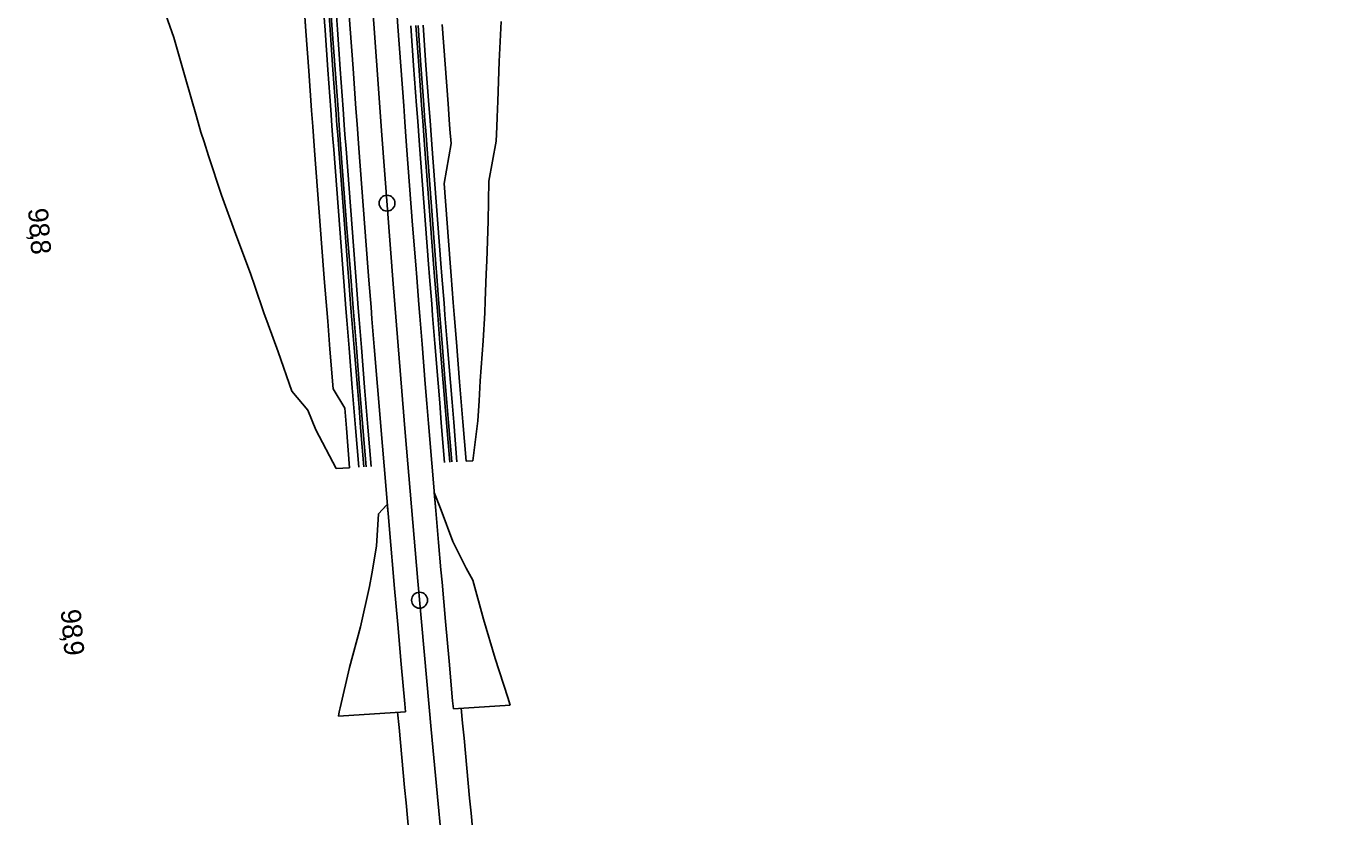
# Model space of a CAD drawing. Extents: x -678487 to -674601, y -1104811 to -1093295.
# Drawn here: x -677536.8 to -677205.5, y -1095748.7 to -1095550.4 of the extents above; entities that cross this region are included whole.
import ezdxf

# ---------------------------------------------------------------- set-up
doc = ezdxf.new("R2010")
doc.units = 0
for name, color, linetype in [('00_MiNGO', 7, 'Continuous'), ('SOxxxxxx_Osa_bod_P', 7, 'Continuous'), ('SOxxxxxx_Staničení_Popis', 7, 'Continuous'), ('SOxxxxxx_ŽSp_hrana', 7, 'Continuous'), ('SOxxxxxx_ŽSp_násyp_hrana', 7, 'Continuous'), ('SOxxxxxx_ŽSp_násyp_plocha', 7, 'Continuous'), ('SOxxxxxx_ŽSp_odvodnění', 7, 'Continuous'), ('SOxxxxxx_ŽSp_zářez_hrana', 7, 'Continuous'), ('SOxxxxxx_ŽSp_zářez_plocha', 7, 'Continuous')]:
    doc.layers.add(name, color=color, linetype=linetype)

msp = doc.modelspace()

# ---------------------------------------------------------------- linework, layer by layer
at = {"layer": '00_MiNGO'}
for radius, start in [(8510.25, 185.218154), (8494.25, 185.221143)]:
    msp.add_arc((-668968.6, -1094948.57), radius, start, 186.854762, dxfattribs=at)
at = {"layer": 'SOxxxxxx_Osa_bod_P'}
msp.add_arc((-668968.6, -1094948.57), 8502.25, 183.991255, 200.113006, dxfattribs=at)
at = {"layer": 'SOxxxxxx_Staničení_Popis'}
for p, q in [((-677446.25, -1095594.77), (-677446.25, -1095594.77)), ((-677438.07, -1095694.43), (-677438.07, -1095694.43))]:
    msp.add_line(p, q, dxfattribs=at)
for centre in [(-677446.25, -1095594.77), (-677438.07, -1095694.43)]:
    msp.add_circle(centre, 2, dxfattribs=at)
at = {"layer": 'SOxxxxxx_ŽSp_hrana'}
for p, q in [((-677456.2, -1095541.06), (-677455.5, -1095551.04)), ((-677444.19, -1095540.47), (-677443.49, -1095550.44)), ((-677455.5, -1095551.04), (-677454.78, -1095561.01)), ((-677443.49, -1095550.44), (-677442.78, -1095560.41)), ((-677454.78, -1095561.01), (-677454.06, -1095570.99)), ((-677442.78, -1095560.41), (-677442.05, -1095570.38)), ((-677454.06, -1095570.99), (-677453.77, -1095574.94)), ((-677442.05, -1095570.38), (-677441.76, -1095574.33)), ((-677441.76, -1095574.33), (-677441.58, -1095576.77)), ((-677453.77, -1095574.94), (-677453.59, -1095577.38)), ((-677453.59, -1095577.38), (-677453.32, -1095580.96)), ((-677441.58, -1095576.77), (-677441.32, -1095580.35)), ((-677453.32, -1095580.96), (-677452.57, -1095590.93)), ((-677441.32, -1095580.35), (-677440.57, -1095590.31)), ((-677452.57, -1095590.93), (-677451.81, -1095600.9)), ((-677440.57, -1095590.31), (-677439.81, -1095600.27)), ((-677439.81, -1095600.27), (-677439.03, -1095610.24)), ((-677451.81, -1095600.9), (-677451.04, -1095610.87)), ((-677439.03, -1095610.24), (-677438.78, -1095613.45)), ((-677451.04, -1095610.87), (-677450.79, -1095614.09)), ((-677450.79, -1095614.09), (-677450.25, -1095620.84)), ((-677438.78, -1095613.45), (-677438.25, -1095620.2)), ((-677438.25, -1095620.2), (-677438.01, -1095623.16)), ((-677450.25, -1095620.84), (-677450.02, -1095623.81)), ((-677450.02, -1095623.81), (-677449.46, -1095630.81)), ((-677438.01, -1095623.16), (-677437.45, -1095630.15)), ((-677437.45, -1095630.15), (-677436.65, -1095640.11)), ((-677449.46, -1095630.81), (-677448.65, -1095640.78)), ((-677436.65, -1095640.11), (-677436.24, -1095645.09)), ((-677448.65, -1095640.78), (-677448.24, -1095645.76)), ((-677448.24, -1095645.76), (-677447.83, -1095650.8)), ((-677436.24, -1095645.09), (-677435.82, -1095650.12)), ((-677435.82, -1095650.12), (-677435, -1095660.02)), ((-677447.83, -1095650.8), (-677447, -1095660.7)), ((-677435, -1095660.02), (-677434.16, -1095669.97)), ((-677447, -1095660.7), (-677446.16, -1095670.67)), ((-677434.16, -1095669.97), (-677433.99, -1095671.94)), ((-677446.16, -1095670.67), (-677445.99, -1095672.64)), ((-677445.99, -1095672.64), (-677445.3, -1095680.63)), ((-677433.99, -1095671.94), (-677433.3, -1095679.92)), ((-677433.3, -1095679.92), (-677432.71, -1095686.77)), ((-677445.3, -1095680.63), (-677444.71, -1095687.49)), ((-677432.71, -1095686.77), (-677432.44, -1095689.87)), ((-677444.71, -1095687.49), (-677444.44, -1095690.59)), ((-677432.44, -1095689.87), (-677431.56, -1095699.81)), ((-677444.44, -1095690.59), (-677443.56, -1095700.54)), ((-677431.56, -1095699.81), (-677430.67, -1095709.75)), ((-677443.56, -1095700.54), (-677442.67, -1095710.5)), ((-677430.67, -1095709.75), (-677429.77, -1095719.7)), ((-677442.67, -1095710.5), (-677441.77, -1095720.45)), ((-677429.77, -1095719.7), (-677429.59, -1095721.67)), ((-677441.77, -1095720.45), (-677441.59, -1095722.44))]:
    msp.add_line(p, q, dxfattribs=at)
at = {"layer": 'SOxxxxxx_ŽSp_násyp_hrana'}
for p, q in [((-677433.41, -1095669.93), (-677432.67, -1095671.87)), ((-677448.35, -1095672.78), (-677448.88, -1095680.84)), ((-677446.45, -1095670.68), (-677448.35, -1095672.78)), ((-677432.67, -1095671.87), (-677429.73, -1095679.71)), ((-677429.73, -1095679.71), (-677426.4, -1095686.4)), ((-677448.88, -1095680.84), (-677450.09, -1095687.81)), ((-677426.4, -1095686.4), (-677424.73, -1095689.4)), ((-677450.09, -1095687.81), (-677450.63, -1095690.96)), ((-677424.73, -1095689.4), (-677422.04, -1095699.23)), ((-677450.63, -1095690.96), (-677452.93, -1095701.12)), ((-677422.04, -1095699.23), (-677419.11, -1095709.04)), ((-677452.93, -1095701.12), (-677455.68, -1095711.31)), ((-677419.11, -1095709.04), (-677415.95, -1095718.82)), ((-677455.68, -1095711.31), (-677458, -1095721.48)), ((-677415.95, -1095718.82), (-677415.32, -1095720.77)), ((-677458.24, -1095722.49), (-677458.47, -1095723.51)), ((-677458, -1095721.48), (-677458.24, -1095722.49))]:
    msp.add_line(p, q, dxfattribs=at)
at = {"layer": 'SOxxxxxx_ŽSp_násyp_plocha'}
for p, q in [((-677458.47, -1095723.51), (-677441.59, -1095722.44)), ((-677415.32, -1095720.77), (-677429.59, -1095721.67))]:
    msp.add_line(p, q, dxfattribs=at)
for points in [[(-677446.18, -1095670.38), (-677448.35, -1095672.78), (-677448.88, -1095680.84), (-677450.09, -1095687.81), (-677450.63, -1095690.96), (-677452.93, -1095701.12), (-677455.68, -1095711.31), (-677458, -1095721.48), (-677458.24, -1095722.49), (-677458.47, -1095723.51)], [(-677441.59, -1095722.44), (-677441.77, -1095720.45), (-677442.67, -1095710.5), (-677443.56, -1095700.54), (-677444.44, -1095690.59), (-677444.71, -1095687.49), (-677445.3, -1095680.63), (-677445.99, -1095672.64), (-677446.18, -1095670.38)], [(-677429.59, -1095721.67), (-677429.77, -1095719.7), (-677430.67, -1095709.75), (-677431.56, -1095699.81), (-677432.44, -1095689.87), (-677432.71, -1095686.77), (-677433.3, -1095679.92), (-677433.99, -1095671.94), (-677434.38, -1095667.37)], [(-677434.38, -1095667.37), (-677432.67, -1095671.87), (-677429.73, -1095679.71), (-677426.4, -1095686.4), (-677424.73, -1095689.4), (-677422.04, -1095699.23), (-677419.11, -1095709.04), (-677415.95, -1095718.82), (-677415.32, -1095720.77)]]:
    msp.add_lwpolyline(points, dxfattribs=at)
at = {"layer": 'SOxxxxxx_ŽSp_odvodnění'}
for p, q in [((-677461.24, -1095541.31), (-677460.54, -1095551.29)), ((-677460.69, -1095541.28), (-677459.99, -1095551.26)), ((-677439, -1095550.22), (-677438.28, -1095560.19)), ((-677438.45, -1095550.19), (-677437.73, -1095560.16)), ((-677460.54, -1095551.29), (-677459.83, -1095561.27)), ((-677459.99, -1095551.26), (-677459.28, -1095561.24)), ((-677438.28, -1095560.19), (-677437.56, -1095570.15)), ((-677437.73, -1095560.16), (-677437.01, -1095570.13)), ((-677459.83, -1095561.27), (-677459.1, -1095571.24)), ((-677459.28, -1095561.24), (-677458.55, -1095571.21)), ((-677437.56, -1095570.15), (-677437.27, -1095574.11)), ((-677437.01, -1095570.13), (-677436.72, -1095574.08)), ((-677459.1, -1095571.24), (-677458.81, -1095575.2)), ((-677458.55, -1095571.21), (-677458.26, -1095575.17)), ((-677437.27, -1095574.11), (-677437.09, -1095576.54)), ((-677436.72, -1095574.08), (-677436.54, -1095576.51)), ((-677458.81, -1095575.2), (-677458.63, -1095577.64)), ((-677458.63, -1095577.64), (-677458.36, -1095581.22)), ((-677458.26, -1095575.17), (-677458.08, -1095577.61)), ((-677458.08, -1095577.61), (-677457.81, -1095581.19)), ((-677437.09, -1095576.54), (-677436.82, -1095580.12)), ((-677436.54, -1095576.51), (-677436.27, -1095580.09)), ((-677436.82, -1095580.12), (-677436.07, -1095590.08)), ((-677436.27, -1095580.09), (-677435.52, -1095590.05)), ((-677458.36, -1095581.22), (-677457.61, -1095591.19)), ((-677457.81, -1095581.19), (-677457.06, -1095591.17)), ((-677436.07, -1095590.08), (-677435.31, -1095600.04)), ((-677435.52, -1095590.05), (-677434.76, -1095600.01)), ((-677457.61, -1095591.19), (-677456.85, -1095601.17)), ((-677457.06, -1095591.17), (-677456.3, -1095601.14)), ((-677435.31, -1095600.04), (-677434.54, -1095610)), ((-677434.76, -1095600.01), (-677433.99, -1095609.97)), ((-677456.85, -1095601.17), (-677456.08, -1095611.14)), ((-677456.3, -1095601.14), (-677455.53, -1095611.11)), ((-677434.54, -1095610), (-677434.29, -1095613.21)), ((-677433.99, -1095609.97), (-677433.74, -1095613.18)), ((-677456.08, -1095611.14), (-677455.83, -1095614.36)), ((-677455.53, -1095611.11), (-677455.28, -1095614.33)), ((-677434.29, -1095613.21), (-677433.76, -1095619.95)), ((-677433.74, -1095613.18), (-677433.21, -1095619.92)), ((-677455.83, -1095614.36), (-677455.3, -1095621.11)), ((-677455.28, -1095614.33), (-677454.75, -1095621.08)), ((-677433.76, -1095619.95), (-677433.52, -1095622.92)), ((-677433.21, -1095619.92), (-677432.97, -1095622.89)), ((-677455.3, -1095621.11), (-677455.06, -1095624.08)), ((-677454.75, -1095621.08), (-677454.51, -1095624.05)), ((-677454.51, -1095624.05), (-677453.95, -1095631.05)), ((-677433.52, -1095622.92), (-677432.96, -1095629.91)), ((-677432.97, -1095622.89), (-677432.41, -1095629.88)), ((-677455.06, -1095624.08), (-677454.5, -1095631.08)), ((-677432.96, -1095629.91), (-677432.15, -1095639.86)), ((-677432.41, -1095629.88), (-677431.61, -1095639.83)), ((-677454.5, -1095631.08), (-677453.69, -1095641.05)), ((-677453.95, -1095631.05), (-677453.14, -1095641.02)), ((-677432.15, -1095639.86), (-677431.75, -1095644.84)), ((-677431.61, -1095639.83), (-677431.2, -1095644.81)), ((-677453.69, -1095641.05), (-677453.28, -1095646.04)), ((-677453.14, -1095641.02), (-677452.73, -1095646.01)), ((-677453.28, -1095646.04), (-677452.87, -1095651.08)), ((-677452.73, -1095646.01), (-677452.32, -1095651.05)), ((-677431.75, -1095644.84), (-677431.33, -1095649.87)), ((-677431.2, -1095644.81), (-677430.78, -1095649.84)), ((-677431.33, -1095649.87), (-677430.51, -1095659.76)), ((-677430.78, -1095649.84), (-677429.96, -1095659.73)), ((-677452.87, -1095651.08), (-677452.04, -1095660.99)), ((-677452.32, -1095651.05), (-677451.49, -1095660.96))]:
    msp.add_line(p, q, dxfattribs=at)
at = {"layer": 'SOxxxxxx_ŽSp_zářez_hrana'}
for p, q in [((-677459.42, -1095541.22), (-677458.71, -1095551.2)), ((-677503.18, -1095543.37), (-677499.75, -1095553.23)), ((-677467.34, -1095541.61), (-677466.63, -1095551.59)), ((-677462.52, -1095541.37), (-677461.82, -1095551.35)), ((-677440.28, -1095550.28), (-677439.56, -1095560.25)), ((-677437.17, -1095550.13), (-677436.46, -1095560.1)), ((-677432.36, -1095549.89), (-677431.64, -1095559.86)), ((-677417.59, -1095549.16), (-677418.11, -1095559.18)), ((-677499.75, -1095553.23), (-677496.97, -1095563.12)), ((-677466.63, -1095551.59), (-677465.92, -1095561.57)), ((-677461.82, -1095551.35), (-677461.11, -1095561.33)), ((-677458.71, -1095551.2), (-677458, -1095561.17)), ((-677439.56, -1095560.25), (-677438.84, -1095570.22)), ((-677436.46, -1095560.1), (-677435.73, -1095570.06)), ((-677431.64, -1095559.86), (-677430.92, -1095569.82)), ((-677418.11, -1095559.18), (-677418.44, -1095569.19)), ((-677496.97, -1095563.12), (-677494.12, -1095573.01)), ((-677465.92, -1095561.57), (-677465.19, -1095571.55)), ((-677461.11, -1095561.33), (-677460.38, -1095571.31)), ((-677458, -1095561.17), (-677457.27, -1095571.15)), ((-677438.84, -1095570.22), (-677438.55, -1095574.17)), ((-677435.73, -1095570.06), (-677435.44, -1095574.01)), ((-677430.92, -1095569.82), (-677430.63, -1095573.77)), ((-677418.44, -1095569.19), (-677418.57, -1095573.16)), ((-677494.12, -1095573.01), (-677492.96, -1095576.93)), ((-677465.19, -1095571.55), (-677464.9, -1095575.51)), ((-677460.38, -1095571.31), (-677460.09, -1095575.26)), ((-677457.27, -1095571.15), (-677456.98, -1095575.11)), ((-677438.55, -1095574.17), (-677438.37, -1095576.6)), ((-677435.44, -1095574.01), (-677435.26, -1095576.45)), ((-677430.63, -1095573.77), (-677430.45, -1095576.2)), ((-677418.57, -1095573.16), (-677418.69, -1095575.6)), ((-677492.96, -1095576.93), (-677492.2, -1095579.35)), ((-677464.9, -1095575.51), (-677464.72, -1095577.95)), ((-677460.09, -1095575.26), (-677459.91, -1095577.7)), ((-677456.98, -1095575.11), (-677456.8, -1095577.54)), ((-677456.8, -1095577.54), (-677456.54, -1095581.13)), ((-677438.37, -1095576.6), (-677438.1, -1095580.18)), ((-677435.26, -1095576.45), (-677434.99, -1095580.02)), ((-677430.45, -1095576.2), (-677430.18, -1095579.78)), ((-677418.69, -1095575.6), (-677418.8, -1095579.2)), ((-677492.2, -1095579.35), (-677491.09, -1095582.89)), ((-677464.72, -1095577.95), (-677464.46, -1095581.53)), ((-677459.91, -1095577.7), (-677459.64, -1095581.28)), ((-677438.1, -1095580.18), (-677437.35, -1095590.14)), ((-677434.99, -1095580.02), (-677434.24, -1095589.98)), ((-677430.18, -1095579.78), (-677431.93, -1095589.86)), ((-677418.8, -1095579.2), (-677420.72, -1095589.28)), ((-677491.09, -1095582.89), (-677487.82, -1095592.76)), ((-677464.46, -1095581.53), (-677463.71, -1095591.51)), ((-677459.64, -1095581.28), (-677458.89, -1095591.26)), ((-677456.54, -1095581.13), (-677455.79, -1095591.1)), ((-677437.35, -1095590.14), (-677436.59, -1095600.11)), ((-677434.24, -1095589.98), (-677433.48, -1095599.94)), ((-677431.93, -1095589.86), (-677431.17, -1095599.82)), ((-677420.72, -1095589.28), (-677420.88, -1095599.28)), ((-677487.82, -1095592.76), (-677484.17, -1095602.6)), ((-677463.71, -1095591.51), (-677462.94, -1095601.49)), ((-677458.89, -1095591.26), (-677458.13, -1095601.23)), ((-677455.79, -1095591.1), (-677455.03, -1095601.07)), ((-677436.59, -1095600.11), (-677435.82, -1095610.07)), ((-677433.48, -1095599.94), (-677432.71, -1095609.9)), ((-677431.17, -1095599.82), (-677430.4, -1095609.78)), ((-677420.88, -1095599.28), (-677421.2, -1095609.29)), ((-677484.17, -1095602.6), (-677480.54, -1095612.44)), ((-677462.94, -1095601.49), (-677462.17, -1095611.46)), ((-677458.13, -1095601.23), (-677457.36, -1095611.21)), ((-677455.03, -1095601.07), (-677454.25, -1095611.04)), ((-677435.82, -1095610.07), (-677435.57, -1095613.28)), ((-677432.71, -1095609.9), (-677432.46, -1095613.11)), ((-677430.4, -1095609.78), (-677430.14, -1095612.99)), ((-677421.2, -1095609.29), (-677421.32, -1095612.52)), ((-677480.54, -1095612.44), (-677479.48, -1095615.62)), ((-677462.17, -1095611.46), (-677461.92, -1095614.69)), ((-677457.36, -1095611.21), (-677457.11, -1095614.43)), ((-677454.25, -1095611.04), (-677454, -1095614.26)), ((-677435.57, -1095613.28), (-677435.03, -1095620.02)), ((-677432.46, -1095613.11), (-677431.93, -1095619.86)), ((-677430.14, -1095612.99), (-677429.61, -1095619.73)), ((-677421.32, -1095612.52), (-677421.58, -1095619.3)), ((-677479.48, -1095615.62), (-677477.15, -1095622.29)), ((-677461.92, -1095614.69), (-677461.39, -1095621.44)), ((-677457.11, -1095614.43), (-677456.57, -1095621.18)), ((-677454, -1095614.26), (-677453.47, -1095621.01)), ((-677435.03, -1095620.02), (-677434.8, -1095622.98)), ((-677431.93, -1095619.86), (-677431.69, -1095622.82)), ((-677429.61, -1095619.73), (-677429.38, -1095622.69)), ((-677421.58, -1095619.3), (-677421.69, -1095622.28)), ((-677477.15, -1095622.29), (-677476.07, -1095625.21)), ((-677461.39, -1095621.44), (-677461.15, -1095624.41)), ((-677456.57, -1095621.18), (-677456.34, -1095624.15)), ((-677453.47, -1095621.01), (-677453.23, -1095623.98)), ((-677453.23, -1095623.98), (-677452.67, -1095630.98)), ((-677434.8, -1095622.98), (-677434.24, -1095629.98)), ((-677431.69, -1095622.82), (-677431.13, -1095629.81)), ((-677429.38, -1095622.69), (-677428.82, -1095629.68)), ((-677421.69, -1095622.28), (-677422.08, -1095629.32)), ((-677476.07, -1095625.21), (-677473.54, -1095632.12)), ((-677461.15, -1095624.41), (-677460.59, -1095631.42)), ((-677456.34, -1095624.15), (-677455.78, -1095631.15)), ((-677434.24, -1095629.98), (-677433.43, -1095639.93)), ((-677431.13, -1095629.81), (-677430.33, -1095639.76)), ((-677428.82, -1095629.68), (-677428.01, -1095639.63)), ((-677422.08, -1095629.32), (-677422.86, -1095639.35)), ((-677473.54, -1095632.12), (-677470.19, -1095641.97)), ((-677460.59, -1095631.42), (-677459.78, -1095641.39)), ((-677455.78, -1095631.15), (-677454.97, -1095641.13)), ((-677452.67, -1095630.98), (-677451.86, -1095640.95)), ((-677433.43, -1095639.93), (-677433.02, -1095644.91)), ((-677430.33, -1095639.76), (-677429.92, -1095644.74)), ((-677428.01, -1095639.63), (-677427.6, -1095644.61)), ((-677422.86, -1095639.35), (-677423.08, -1095644.35)), ((-677470.19, -1095641.97), (-677466.09, -1095646.75)), ((-677459.78, -1095641.39), (-677456.88, -1095646.24)), ((-677454.97, -1095641.13), (-677454.56, -1095646.11)), ((-677451.86, -1095640.95), (-677451.46, -1095645.94)), ((-677466.09, -1095646.75), (-677464.14, -1095651.71)), ((-677456.88, -1095646.24), (-677456.46, -1095651.28)), ((-677454.56, -1095646.11), (-677454.15, -1095651.15)), ((-677451.46, -1095645.94), (-677451.04, -1095650.98)), ((-677433.02, -1095644.91), (-677432.61, -1095649.94)), ((-677429.92, -1095644.74), (-677429.5, -1095649.76)), ((-677427.6, -1095644.61), (-677427.19, -1095649.63)), ((-677423.08, -1095644.35), (-677423.48, -1095649.37)), ((-677432.61, -1095649.94), (-677431.78, -1095659.83)), ((-677429.5, -1095649.76), (-677428.68, -1095659.66)), ((-677427.19, -1095649.63), (-677426.36, -1095659.53)), ((-677423.48, -1095649.43), (-677424.66, -1095659.43)), ((-677423.48, -1095649.37), (-677423.48, -1095649.43)), ((-677464.14, -1095651.71), (-677459.01, -1095661.39)), ((-677456.46, -1095651.28), (-677455.63, -1095661.2)), ((-677454.15, -1095651.15), (-677453.32, -1095661.06)), ((-677451.04, -1095650.98), (-677450.21, -1095660.89))]:
    msp.add_line(p, q, dxfattribs=at)
at = {"layer": 'SOxxxxxx_ŽSp_zářez_plocha'}
for p, q in [((-677424.66, -1095659.43), (-677426.36, -1095659.53)), ((-677455.63, -1095661.2), (-677459.01, -1095661.39))]:
    msp.add_line(p, q, dxfattribs=at)
for points in [[(-677459.01, -1095661.39), (-677464.14, -1095651.71), (-677466.09, -1095646.75), (-677470.19, -1095641.97), (-677473.54, -1095632.12), (-677476.07, -1095625.21), (-677477.15, -1095622.29), (-677479.48, -1095615.62), (-677480.54, -1095612.44), (-677484.17, -1095602.6), (-677487.82, -1095592.76), (-677491.09, -1095582.89), (-677492.2, -1095579.35), (-677492.96, -1095576.93), (-677494.12, -1095573.01), (-677496.97, -1095563.12), (-677499.75, -1095553.23), (-677503.18, -1095543.37)], [(-677467.34, -1095541.61), (-677466.63, -1095551.59), (-677465.92, -1095561.57), (-677465.19, -1095571.55), (-677464.9, -1095575.51), (-677464.72, -1095577.95), (-677464.46, -1095581.53), (-677463.71, -1095591.51), (-677462.94, -1095601.49), (-677462.17, -1095611.46), (-677461.92, -1095614.69), (-677461.39, -1095621.44), (-677461.15, -1095624.41), (-677460.59, -1095631.42), (-677459.78, -1095641.39), (-677456.88, -1095646.24), (-677456.46, -1095651.28), (-677455.63, -1095661.2)], [(-677426.36, -1095659.53), (-677427.19, -1095649.63), (-677427.6, -1095644.61), (-677428.01, -1095639.63), (-677428.82, -1095629.68), (-677429.38, -1095622.69), (-677429.61, -1095619.73), (-677430.14, -1095612.99), (-677430.4, -1095609.78), (-677431.17, -1095599.82), (-677431.93, -1095589.86), (-677430.18, -1095579.78), (-677430.45, -1095576.2), (-677430.63, -1095573.77), (-677430.92, -1095569.82), (-677431.64, -1095559.86), (-677432.36, -1095549.89)], [(-677417.59, -1095549.16), (-677418.11, -1095559.18), (-677418.44, -1095569.19), (-677418.57, -1095573.16), (-677418.69, -1095575.6), (-677418.8, -1095579.2), (-677420.72, -1095589.28), (-677420.88, -1095599.28), (-677421.2, -1095609.29), (-677421.32, -1095612.52), (-677421.58, -1095619.3), (-677421.69, -1095622.28), (-677422.08, -1095629.32), (-677422.86, -1095639.35), (-677423.08, -1095644.35), (-677423.48, -1095649.37), (-677423.48, -1095649.43), (-677424.66, -1095659.43)]]:
    msp.add_lwpolyline(points, dxfattribs=at)

# ---------------------------------------------------------------- texts
at = {"layer": 'SOxxxxxx_Staničení_Popis'}
for s, rotation, p in [('98', 274.3589, (-677536.41, -1095596.18)), (',', 274.3589, (-677535.92, -1095602.53)), ('8', 274.3589, (-677535.8, -1095604.12)), ('98', 275.0328, (-677528.2, -1095696.9)), (',', 275.0328, (-677527.64, -1095703.25)), ('9', 275.0328, (-677527.5, -1095704.84))]:
    msp.add_text(s, height=5, rotation=rotation, dxfattribs=at).set_placement(p)

doc.saveas('drawing.dxf')
